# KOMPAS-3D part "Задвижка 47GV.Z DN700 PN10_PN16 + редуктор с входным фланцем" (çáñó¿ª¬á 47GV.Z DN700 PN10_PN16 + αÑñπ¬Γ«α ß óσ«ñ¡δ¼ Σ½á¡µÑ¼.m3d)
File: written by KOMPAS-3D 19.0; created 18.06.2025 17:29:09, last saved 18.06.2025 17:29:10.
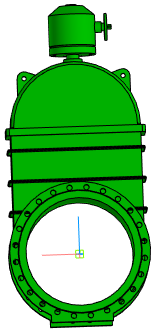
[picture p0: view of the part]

Document properties: Полное имя файла: Задвижка 47GV.Z DN700 PN10_PN16 + редуктор с входным валом.a3d

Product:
- Part/product: Задвижка 47GV.Z DN700 PN10_PN16 + редуктор с входным фланцем
    Масса: 2095.53
  - Body: Тело 1
      Масса: 2096.31

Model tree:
1. Операция без истории:1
